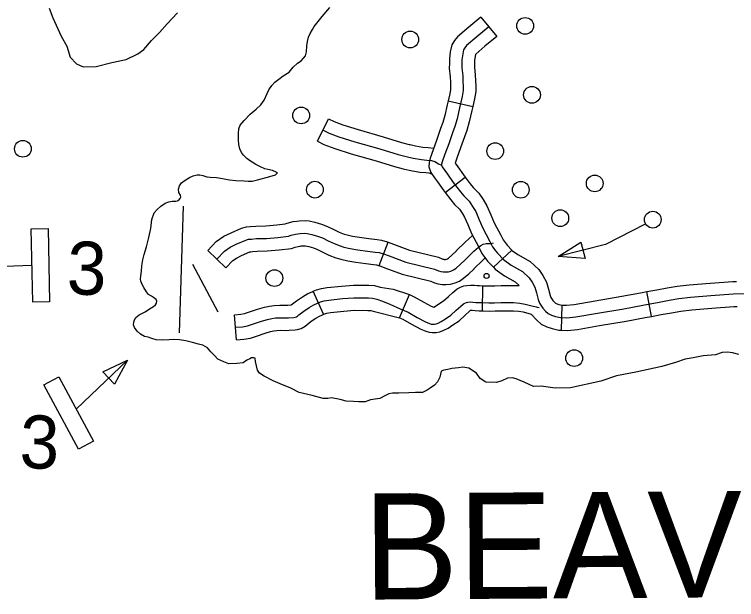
# Model space of a CAD drawing. Extents: x 653372 to 905732, y 627442 to 787275.
# Drawn here: x 714580 to 718889, y 740646 to 744138 of the extents above; entities that cross this region are included whole.
import ezdxf

# ---------------------------------------------------------------- set-up
doc = ezdxf.new("R2010")
doc.units = 0
for name, color, linetype in [('32', 7, 'Continuous'), ('45', 7, 'Continuous'), ('5', 7, 'Continuous'), ('56', 7, 'Continuous'), ('9', 7, 'Continuous')]:
    doc.layers.add(name, color=color, linetype=linetype)

msp = doc.modelspace()

# ---------------------------------------------------------------- linework, layer by layer
at = {"layer": '32'}
for p, q in [((717362.1, 744121.6), (717458.1, 744006.4)), ((717168.6, 743622.5), (717314.9, 743589.3)), ((717149.9, 743075.7), (717269.3, 743166.5)), ((717437.9, 742629.1), (717547.2, 742731.8)), ((717372.8, 742369.5), (717374.2, 742519.5)), ((716424.9, 742349.3), (716363.3, 742486.1)), ((718380.6, 742336.4), (718353.3, 742483.9)), ((716878, 742328.6), (716937.8, 742466.2)), ((717843.8, 742253.5), (717848.3, 742403.4)), ((715905.4, 742196.7), (715893.5, 742346.2))]:
    msp.add_line(p, q, dxfattribs=at)
for points in [[(717362.1, 744121.6), (717291, 744062.4), (717223.3, 744004.4), (717206.4, 743982.7), (717190, 743956.1), (717180.8, 743915.5), (717175.2, 743872.5), (717175.5, 743844.6), (717174.6, 743817.3), (717180.4, 743765.3), (717181.7, 743734.9), (717182.8, 743708.9), (717182.6, 743691.1), (717177.9, 743663.5), (717168.6, 743622.5)], [(717410.1, 744064), (717339.4, 744005.1), (717277.8, 743952.3), (717268.1, 743939.8), (717260.4, 743927.3), (717254.7, 743902.4), (717250.2, 743868), (717250.5, 743843.9), (717249.8, 743820.3), (717255.2, 743771.1), (717256.6, 743738.1), (717257.8, 743710), (717257.5, 743684.4), (717251.5, 743649), (717236.2, 743581.5), (717220.9, 743515.6), (717207.3, 743469.7), (717193.8, 743432.2), (717171.7, 743366.9), (717149.2, 743305.1), (717132.5, 743258.9), (717129.2, 743244.2), (717129, 743238.3), (717132.1, 743227.9), (717147.5, 743206.7)], [(717458.1, 744006.4), (717387.9, 743947.8), (717332.4, 743900.3), (717330.6, 743898.1), (717328.6, 743889.2), (717325.3, 743863.6), (717325.5, 743843.2), (717324.9, 743823.3), (717330, 743776.9), (717331.6, 743741.3), (717332.8, 743711.1), (717332.4, 743677.7), (717325.1, 743634.4), (717314.9, 743589.3)], [(717168.6, 743622.5), (717163.1, 743598.3), (717148.4, 743534.7), (717136, 743493.1), (717123, 743456.9), (717100.9, 743391.8), (717078.7, 743330.7), (717060.5, 743280.1), (717054.4, 743253.9), (717053.6, 743228.4), (717063.9, 743194.2), (717087.1, 743162.1), (717103.6, 743140.2), (717137.7, 743091.8), (717149.9, 743075.7)], [(717314.9, 743589.3), (717309.3, 743564.8), (717293.5, 743496.4), (717278.6, 743446.3), (717264.7, 743407.5), (717242.5, 743342.1), (717219.7, 743279.6), (717209, 743249.7), (717224.9, 743228.5), (717258.8, 743180.3), (717269.3, 743166.5)], [(717147.5, 743206.7), (717164.3, 743184.3), (717198.2, 743136.1), (717241.4, 743079.2), (717261.8, 743055.5), (717293.2, 743023), (717314, 742992.9), (717332.7, 742961.8), (717353.9, 742913), (717375, 742862.1), (717415, 742787.1), (717432.7, 742752.1), (717453.5, 742724.9), (717462, 742713), (717497.3, 742675.4), (717543.5, 742642.5), (717612.2, 742604), (717651, 742566.6), (717668.9, 742540.4), (717684.8, 742510.4), (717695.6, 742477.6), (717705.2, 742438), (717713.6, 742415.5), (717732.2, 742386), (717749.6, 742367.4), (717765.6, 742352.5), (717785.3, 742343.2), (717808.7, 742335.6), (717838.7, 742328.7), (717877, 742327.5), (717929.4, 742332.8), (718058.9, 742355.5), (718217.2, 742382.2), (718330.3, 742403.4), (718426.3, 742421.2), (718487.6, 742432.1), (718545, 742442.2), (718614.1, 742450), (718736.4, 742460.1), (718869.5, 742469.9), (718958.2, 742472.1)], [(717269.3, 743166.5), (717299.7, 743126.4), (717317.2, 743106.1), (717351.5, 743070.7), (717377, 743033.6), (717399.5, 742996.2), (717422.9, 742942.2), (717442.8, 742894.2), (717481.6, 742821.7), (717496.5, 742792.2), (717513.9, 742769.4), (717520.2, 742760.5), (717547.2, 742731.8)], [(717149.9, 743075.7), (717183.1, 743032), (717206.4, 743004.9), (717235, 742975.4), (717250.9, 742952.2), (717265.9, 742927.4), (717284.8, 742883.7), (717307.1, 742830), (717348.5, 742752.6), (717368.9, 742712.1), (717393.1, 742680.5), (717403.7, 742665.4), (717437.9, 742629.1)], [(717546.8, 742732.2), (717583.7, 742706), (717657.3, 742664.7), (717708.6, 742615.2), (717733.3, 742579.3), (717754, 742539.9), (717767.8, 742498.3), (717777.1, 742460), (717781.2, 742448.9), (717791.8, 742432), (717802.6, 742420.6), (717808.2, 742415.3), (717813, 742413), (717828.7, 742407.9), (717848.4, 742403.4), (717848.3, 742403.4)], [(717437.9, 742629.1), (717447.7, 742618.6), (717503.3, 742579), (717567.1, 742543.3), (717591.7, 742519.6)], [(716363.3, 742486.1), (716382.4, 742494.7), (716413.2, 742502.3), (716445.9, 742507.7), (716531.2, 742516.9), (716603, 742522.6), (716695.1, 742521.9), (716728.4, 742519.6), (716762.9, 742511.6), (716839.8, 742498.3), (716937.8, 742466.2)], [(716937.8, 742466.2), (716965.9, 742453.9), (717022.2, 742420.5), (717066.1, 742397.8), (717082.4, 742391.5), (717092.1, 742396.4), (717113.3, 742410.3), (717140.7, 742428.8), (717169.2, 742454.4), (717196.4, 742479.8), (717221.7, 742501.4), (717241, 742510.3), (717261.2, 742518.3), (717279, 742521.1), (717301.4, 742523.5), (717325.6, 742522), (717341.1, 742520.1), (717355.7, 742519.7), (717374.2, 742519.5)], [(717374.2, 742519.5), (717379.8, 742519.5), (717413.9, 742518.4), (717445.9, 742518.9), (717484.3, 742520.2), (717537.2, 742520.1), (717591.7, 742519.6)], [(718353.3, 742483.9), (718412.9, 742494.9), (718474.6, 742506), (718534.3, 742516.5), (718606.8, 742524.6), (718730.6, 742534.8), (718865.8, 742544.8), (718889, 742545.4)], [(715893.5, 742346.2), (715930.7, 742349.2), (715952, 742352.7), (715977.2, 742361.1), (716031.3, 742379.8), (716073, 742391.2), (716101.8, 742397.4), (716130.2, 742401.5), (716164.2, 742403.4), (716196, 742403), (716212.1, 742403.3), (716231.9, 742404.6), (716263.6, 742429.4), (716298.2, 742452.2), (716331.2, 742471.9), (716357, 742483.2), (716363.3, 742486.1)], [(717848.3, 742403.4), (717874.4, 742402.6), (717919.1, 742407.2), (718046.2, 742429.4), (718204, 742456.1), (718316.6, 742477.1), (718353.3, 742483.9)], [(715899.4, 742271.4), (715939.9, 742274.7), (715970, 742279.7), (716001.3, 742290), (716053.5, 742308.1), (716090.7, 742318.3), (716115, 742323.5), (716137.7, 742326.8), (716165.8, 742328.4), (716196.3, 742328), (716215.3, 742328.4), (716246.8, 742330.4), (716255.7, 742331.6), (716262.6, 742333.4), (716269.6, 742337.6), (716277.7, 742345.2), (716307.5, 742368.4), (716338.1, 742388.7), (716365.6, 742405.1), (716387.6, 742414.7), (716407, 742423.5), (716428.3, 742428.8), (716456, 742433.4), (716538.1, 742442.2), (716605.7, 742447.6), (716692.3, 742446.9), (716717.3, 742445.2), (716741.7, 742439.5), (716776.3, 742427.2), (716820, 742408.7), (716881.2, 742381.7), (716928.5, 742361.1), (716982.7, 742329), (717032.1, 742303.4), (717056.9, 742293.8), (717067.1, 742290.5), (717075, 742289.8), (717086.3, 742289.9), (717096.2, 742291.6), (717109.1, 742296.6), (717126.6, 742305.5), (717151.7, 742321.9), (717183.8, 742343.6), (717216.7, 742373.1), (717243.2, 742397.9), (717259.4, 742411.7), (717267.4, 742415.4), (717277.8, 742419.5), (717285.7, 742420.7), (717300, 742422.3), (717315.7, 742421.3), (717332.4, 742419.3), (717351.1, 742418.8), (717375.2, 742418.5), (717410.1, 742417.5), (717444.5, 742417.9), (717482.5, 742419.3), (717533.6, 742419.2), (717557.7, 742419), (717596.7, 742415.8), (717628, 742410), (717667, 742399.9), (717692.4, 742392.3), (717699.2, 742390.6), (717710.5, 742389.6)], [(718380.6, 742336.4), (718439.7, 742347.4), (718500.7, 742358.3), (718555.7, 742367.9), (718621.4, 742375.3), (718742.3, 742385.3), (718873.3, 742394.9), (718892.8, 742395.4)], [(715905.4, 742196.7), (715949, 742200.1), (715988.1, 742206.6), (716025.4, 742219), (716075.8, 742236.5), (716108.5, 742245.4), (716128.2, 742249.6), (716145.2, 742252.1), (716167.5, 742253.4), (716196.6, 742253), (716218.5, 742253.4), (716254.2, 742255.7), (716270, 742257.9), (716291.8, 742263.4), (716315.2, 742277.5), (716326.7, 742288.2), (716351.3, 742307.5), (716378, 742325.1), (716400.1, 742338.3), (716418.1, 742346.2), (716424.9, 742349.3)], [(716424.9, 742349.3), (716431.6, 742352.3), (716443.5, 742355.3), (716466.2, 742359), (716545.1, 742367.5), (716608.4, 742372.5), (716689.4, 742372), (716706.2, 742370.8), (716720.6, 742367.5), (716878, 742328.6)], [(716878, 742328.6), (716897.4, 742320.1), (716949.4, 742289.3), (717004.3, 742260.8), (717035.1, 742248.9), (717055.2, 742242.5), (717075.1, 742240.7), (717096.2, 742241), (717119.3, 742244.9), (717142.8, 742254), (717167.3, 742266.4), (717196.4, 742285.4), (717233.2, 742310.3), (717270.5, 742343.8), (717296.3, 742367.9), (717301.9, 742372.6), (717304.9, 742373), (717312.2, 742372.5), (717330, 742370.4), (717352.7, 742369.7), (717372.8, 742369.5)], [(717372.8, 742369.5), (717376.8, 742369.5), (717412.6, 742368.4), (717449.5, 742368.9), (717486.9, 742370.2), (717536.4, 742370.1), (717557.5, 742369.9), (717589.9, 742367.3), (717614.9, 742362.6), (717662.8, 742350.3)], [(717662.8, 742350.3), (717696.6, 742314.2), (717723.1, 742289.7), (717757.5, 742273.3), (717788.6, 742263.3), (717829, 742253.9), (717843.8, 742253.5)], [(717843.8, 742253.5), (717879.7, 742252.4), (717939.6, 742258.5), (718071.6, 742281.6), (718230.3, 742308.4), (718344.1, 742329.6), (718380.6, 742336.4)]]:
    msp.add_lwpolyline(points, dxfattribs=at)
at = {"layer": '45'}
for p, q in [((716388.2, 743381.2), (716454.9, 743515.5)), ((716756.6, 742639.5), (716810.7, 742779.4)), ((715842.1, 742626.3), (715733.7, 742729.9))]:
    msp.add_line(p, q, dxfattribs=at)
for points in [[(716454.9, 743515.5), (716487.6, 743499.3), (716540.4, 743479), (716631.8, 743450.6), (716781, 743407.7), (716889.2, 743374.2), (716934.6, 743362.6), (716941.1, 743361.1)], [(716421.6, 743448.4), (716457.4, 743430.5), (716515.8, 743408.1), (716610.3, 743378.7), (716759.6, 743335.8), (716868.8, 743302.1), (716916.6, 743289.8), (716959.6, 743279.6), (717008.6, 743272.3), (717041.8, 743269.3), (717067.7, 743266.6), (717088.2, 743260), (717111.4, 743247), (717129, 743238.3)], [(716388.2, 743381.2), (716427.2, 743361.8), (716491.2, 743337.2), (716588.9, 743306.8), (716738.2, 743264), (716848.4, 743229.9), (716898.7, 743217), (716906.6, 743215.1)], [(716941.1, 743361.1), (716973.8, 743353.3), (717017.5, 743346.8), (717049, 743343.9), (717082.2, 743340.4)], [(716906.6, 743215.1), (716945.4, 743205.9), (716999.7, 743197.8), (717034.5, 743194.7), (717052.3, 743192.8), (717068.7, 743187.5)], [(715733.7, 742729.9), (715784.5, 742783.1), (715829.2, 742814.4), (715872.3, 742835.2), (715935.3, 742863.1), (715964.1, 742870.6), (715987.3, 742872.6), (716019.9, 742875.4), (716080.9, 742876.5), (716144.8, 742882.1), (716196.4, 742887.8), (716207.1, 742892.1), (716243, 742901.6), (716265.1, 742904.5)], [(716265.1, 742904.5), (716278.3, 742906.3), (716314.9, 742907.8), (716338.2, 742905.5), (716373.2, 742898.8), (716412.5, 742886.5), (716447.3, 742873.4), (716485.2, 742855.1), (716517.8, 742839.4), (716547.2, 742827.5), (716564.7, 742822.5), (716598.2, 742815), (716639.4, 742808.3), (716695.7, 742800.8), (716743.7, 742794.4), (716770.8, 742790.6), (716804.6, 742781.7), (716810.7, 742779.4)], [(715787.9, 742678.1), (715833.6, 742725.9), (715867.3, 742749.5), (715903.7, 742767.1), (715960.1, 742792), (715976.9, 742796.4), (715993.7, 742797.9), (716023.8, 742800.4), (716084.8, 742801.6), (716152.2, 742807.4), (716214.8, 742814.4), (716230.8, 742820.8), (716257.6, 742827.9), (716284.7, 742831.5), (716312.8, 742832.6), (716327.5, 742831.2), (716354.9, 742825.9), (716388, 742815.6), (716417.7, 742804.4), (716452.6, 742787.6), (716487.4, 742770.8), (716522.8, 742756.4), (716546.3, 742749.8), (716583.9, 742741.3), (716628.4, 742734.1), (716685.8, 742726.4), (716733.5, 742720.1), (716756.1, 742716.9), (716781.5, 742710.3), (716816, 742696.9), (716916.1, 742659.9)], [(717217.8, 742728.1), (717218.6, 742728.9), (717269, 742779), (717313, 742819)], [(716810.7, 742779.4), (716842.5, 742767.1), (716938.2, 742731.7), (717110.5, 742689), (717136.8, 742678.4), (717141.5, 742676.9), (717143.3, 742676.7), (717151.4, 742676.7), (717156.3, 742677), (717158.8, 742677.7), (717163.6, 742679.8), (717169.9, 742684), (717189.8, 742700.9), (717217.8, 742728.1)], [(716916.1, 742659.9), (717087.4, 742617.4), (717111.2, 742607.9), (717124.7, 742603.5), (717138.1, 742601.6), (717153.8, 742601.7), (717169.6, 742602.7), (717184.5, 742607.1), (717199.5, 742613.6), (717215, 742623.9), (717240.3, 742645.3), (717271.2, 742675.4), (717320.7, 742724.6), (717349, 742750.3), (717363.5, 742759.7), (717376.1, 742766.7), (717395.4, 742770.6), (717414.6, 742772), (717423.9, 742771.2), (717437.8, 742775.2)], [(715842.1, 742626.3), (715882.7, 742668.8), (715905.4, 742684.6), (715935.2, 742699), (715984.9, 742721), (715989.8, 742722.3), (716000.1, 742723.2), (716027.6, 742725.5), (716088.8, 742726.6), (716159.6, 742732.8), (716233.3, 742741), (716254.4, 742749.5), (716272.1, 742754.1), (716284.9, 742755.8)], [(716284.9, 742755.8), (716291.2, 742756.7), (716310.7, 742757.5), (716316.8, 742756.9), (716336.6, 742753.1), (716363.6, 742744.7), (716388.1, 742735.4), (716420.1, 742720), (716456.9, 742702.2), (716498.5, 742685.4), (716527.8, 742677.1), (716569.6, 742667.6), (716617.5, 742659.9), (716675.9, 742652.1), (716723.4, 742645.8), (716741.3, 742643.3), (716758.3, 742638.8), (716756.6, 742639.5)], [(717322.4, 742620.6), (717323.8, 742621.9), (717372.3, 742670.2), (717389.2, 742685.5)], [(716756.6, 742639.5), (716789.4, 742626.8), (716894, 742588.1), (717064.3, 742545.9), (717085.7, 742537.3), (717107.8, 742530.2), (717132.9, 742526.6), (717156.3, 742526.7), (717183, 742528.4), (717210.2, 742536.6), (717235.4, 742547.4), (717260.2, 742563.9), (717290.7, 742589.8), (717322.4, 742620.6)]]:
    msp.add_lwpolyline(points, dxfattribs=at)
at = {"layer": '5'}
msp.add_lwpolyline([(715587.2, 742993.5), (715563.8, 742237.8)], dxfattribs=at)
at = {"layer": '56'}
for p, q in [((717824.7, 742693), (717960.5, 742780.1)), ((717960.5, 742780.1), (717985.6, 742681.2)), ((717985.6, 742681.2), (717824.7, 742693)), ((715107.7, 742006), (715253.7, 742074.6)), ((715253.7, 742074.6), (715178.1, 741932.1)), ((715178.1, 741932.1), (715107.7, 742006))]:
    msp.add_line(p, q, dxfattribs=at)
for points in [[(714680.5, 742857.8), (714780.5, 742859.8), (714789.2, 742422.4), (714689.2, 742420.4)], [(714756.3, 741928.8), (714844.4, 741976.1), (715051.4, 741590.7), (714963.2, 741543.4)]]:
    msp.add_lwpolyline(points, close=True, dxfattribs=at)
for points in [[(718344.3, 742886.7), (718107.8, 742764.8), (717824.7, 742693)], [(715642.1, 742647.3), (715794.4, 742363.5)], [(714684.9, 742639.1), (714354.5, 742627)], [(714947.9, 741783.4), (715253.7, 742074.6)]]:
    msp.add_lwpolyline(points, dxfattribs=at)
for centre, radius in [((717627.6, 744069.7), 50), ((716941.8, 743988.4), 50), ((717668.1, 743658.4), 50), ((716290.9, 743535.3), 50), ((714630.6, 743336.4), 50), ((717449, 743322.8), 50), ((718042.6, 743129.9), 50), ((716373.1, 743092.4), 50), ((717601.2, 743092.1), 50), ((717837.1, 742922.6), 50), ((718388.9, 742913.7), 50), ((716131.1, 742564.8), 50), ((717397.2, 742577.9), 15), ((717920, 742087.4), 50)]:
    msp.add_circle(centre, radius, dxfattribs=at)
at = {"layer": '9'}
for points in [[(714787.7, 744176.3), (714808.9, 744117.1), (714857.9, 744009), (714891.7, 743949.4), (714912.7, 743884), (714951.2, 743843.1), (714990.4, 743825.2), (715067.7, 743827), (715160.5, 743851.4), (715246.7, 743869.8), (715316.7, 743903.2), (715353, 743929.3), (715398.5, 743982.3), (715445.9, 744031), (715491.4, 744082), (715553.9, 744147)], [(715917.4, 743389.5), (715916.1, 743427.7), (715919.1, 743456.2), (715927.1, 743477.2), (715951.3, 743505.1), (715987.4, 743542.2), (716022.3, 743573), (716049.6, 743598.7), (716070.6, 743626.7), (716088.7, 743666.5), (716098.9, 743688.5), (716116.7, 743713.4), (716134.2, 743734.1), (716158.1, 743752.5), (716183.1, 743770.8), (716218.7, 743793.1), (716243, 743823.1), (716269.2, 743847.8), (716291.9, 743862), (716304, 743877.5), (716317.2, 743892), (716322.1, 743915.2), (716325.3, 743950.1), (716328.2, 743976.5), (716334.3, 744002.9), (716345.6, 744024.8), (716357.9, 744047.8), (716369.1, 744066.5), (716417.2, 744125), (716461.2, 744178.8)], [(715399.2, 742913.8), (715413.2, 742953.9), (715431.7, 742975.1), (715453, 742993.2), (715479.2, 743011.2), (715502.2, 743020.4), (715520.9, 743024.6), (715543.8, 743023.1), (715552.8, 743024.9), (715560.9, 743030.5), (715569, 743039.2), (715572.2, 743048), (715570.6, 743058.9), (715560.2, 743075.1), (715558.8, 743094.9), (715565.3, 743114.5), (715576.8, 743133.9), (715599, 743149.1), (715625.2, 743165.1), (715646.2, 743174.3), (715670.1, 743180.6), (715687, 743181), (715704.6, 743176.5), (715728.2, 743169.9), (715748.8, 743166.3), (715786.3, 743164.2), (715820.7, 743158.2), (715863, 743151), (715901.5, 743147.9), (715950.8, 743144.4), (715974.5, 743142.7), (715999, 743144), (716030.9, 743150.9), (716103.6, 743170.4), (716137.6, 743181.3), (716146.7, 743188.9), (716148.8, 743193.8), (716141, 743196), (716119.6, 743207.5), (716092.1, 743212.3), (716074.4, 743216.8), (716049.1, 743229.4), (716019.8, 743242.2), (715999.5, 743256.6), (715982, 743267), (715966.5, 743279.4), (715946.3, 743297.8), (715935, 743314.9), (715924.8, 743337), (715919.6, 743361.9), (715917.4, 743389.5)], [(715859.5, 742054), (715830.4, 742065.9), (715794.3, 742081.8), (715773.2, 742102.2), (715752.1, 742124.6), (715732.1, 742147.9), (715704.9, 742163.6), (715677.4, 742170.3), (715642.1, 742180.3), (715601.8, 742189.4), (715565.4, 742195.5), (715531.9, 742198.4), (715503.2, 742196.3), (715464.6, 742194.5), (715426.1, 742196.7), (715400.6, 742203.4), (715377.1, 742212), (715356.5, 742216.6), (715333.2, 742231.1), (715312, 742248.6), (715295.8, 742270.8), (715290.3, 742285.8), (715292.8, 742302.5), (715297.2, 742316.3), (715303.5, 742328.9), (715323.8, 742346.1), (715360.9, 742363.8), (715386.1, 742380.8), (715410.3, 742395.9), (715422.4, 742404.5), (715428.7, 742414.2), (715429.1, 742428), (715425.4, 742438), (715409.9, 742449.3), (715397.3, 742456.6), (715380.8, 742467), (715367.4, 742482.3), (715351.4, 742508.5), (715342.1, 742527.5), (715334.8, 742546.5), (715333.1, 742558.4), (715334.7, 742578.2), (715338.5, 742606.7), (715339.6, 742638.7), (715346.5, 742673.1), (715353.4, 742706.2), (715368.6, 742751.5), (715382.1, 742807.5), (715393.6, 742860.5), (715399.2, 742913.8)], [(718902.2, 742109), (718864.9, 742118), (718835.4, 742122.9), (718803.6, 742119.9), (718763.7, 742107.2), (718690.4, 742101.5), (718630.7, 742089.5), (718583, 742081), (718525, 742061), (718443.3, 742037.7), (718287, 742004), (718172.8, 741981.4), (718079.5, 741948.7), (717898.5, 741909.2), (717806.2, 741907.2), (717722.8, 741918.9), (717677.3, 741918.3), (717620.7, 741943.8), (717573.8, 741963), (717552.5, 741969.7), (717522.6, 741968.5), (717488.5, 741951.7), (717456.5, 741940.8), (717393.5, 741942.8), (717358.6, 741965.6), (717337.6, 741997.8), (717291, 742026.8), (717255.6, 742033.8), (717229.8, 742028.7), (717190.2, 742025.9), (717166.2, 742018.7), (717142.4, 742015.5), (717126.4, 742010), (717121.9, 741992.4), (717117.4, 741972.7), (717104.7, 741945.4), (717086.3, 741926.2), (717060.1, 741907.2), (717041.9, 741895.9), (717015.8, 741882.8), (716973.5, 741882.2), (716933.5, 741879.4), (716874.1, 741877.2), (716836.6, 741878.3), (716814.7, 741875), (716794.6, 741863.7), (716760.5, 741847), (716704.9, 741838.8), (716672.8, 741825.9), (716635.3, 741827), (716603.7, 741827.9), (716560.3, 741831.2), (716523, 741840.3), (716471.9, 741849.7), (716450, 741846.4), (716422.3, 741845.3), (716355.7, 741865.1), (716279.1, 741881.2), (716228.5, 741908.4), (716166, 741934), (716123, 741951.2), (716070.5, 741980.4), (716043.3, 741997.1), (716030.4, 742015.3), (716018.1, 742067.1), (716016.7, 742086.9), (716008.9, 742089.1), (715995.1, 742089.5), (715985, 742083.9), (715966.9, 742074.5), (715944.7, 742059.4), (715907, 742054.6), (715859.5, 742054)]]:
    msp.add_lwpolyline(points, dxfattribs=at)

# ---------------------------------------------------------------- texts
at = {"layer": '56'}
for p in [(714889.7, 742468.9), (714607.8, 741431.7)]:
    msp.add_text('3', height=316.8, rotation=358.28, dxfattribs=at).set_placement(p)
at = {"layer": '9'}
msp.add_text('BEAVER  LAKE', height=633.599, rotation=0.3656, dxfattribs=at).set_placement((716663.5, 740646))

doc.saveas('drawing.dxf')
